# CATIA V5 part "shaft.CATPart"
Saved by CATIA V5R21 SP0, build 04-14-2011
Part number: Part1
Bounding box of the stored display mesh (mm): x -100 to 100, y -25 to 25, z -24.818 to 24.818
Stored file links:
  D:\CATIA V5R21 E-RESOURCES\CATIA-V5R21\catia-v5r21-prt\c16-catia-v5r20-prt\Cylindrical Joint(Fig16-18)\CAT_V5R21_shaft.CATPart
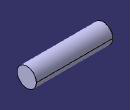
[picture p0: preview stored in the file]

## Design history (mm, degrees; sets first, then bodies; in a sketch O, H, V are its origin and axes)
Body1 (main body)
  Sketch1 on yz-plane, origin (0, 0, 0), H (0, 1, 0), V (0, 0, 1)
    circle A1 centre (0, 0) radius 25
    radius A1 = 25
  Pad1: profile Sketch1, direction (1, 0, 0), length 100, mirrored extent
